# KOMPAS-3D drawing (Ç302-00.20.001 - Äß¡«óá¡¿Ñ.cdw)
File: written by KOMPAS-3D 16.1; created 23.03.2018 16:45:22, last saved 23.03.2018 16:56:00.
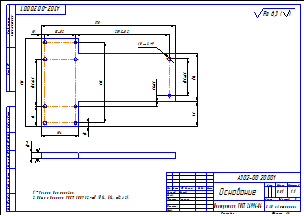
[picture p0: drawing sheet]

Sheet 1: A3, landscape

Title block, sheet 1: name: Основание; designation: А302-00.20.001; material: Полипропилен  ГОСТ 26996-86; mass: 0,81; scale: 1:1; sheets: 1; organisation: ЗАО «Астерион»; sheet format: A3; stored path: \\192.168.87.28\Konstructor_doc\Мембранные насосы\Мембранный электропривод\А302-00.00.000 - ASTRA-302 (МЭ200)\Чертежи\А302-00.20.001 - Основание.cdw; drawn by: Милов; technical control: Лучихин

Views: Вид 1, Спереди, Проекционный вид 2
Referenced files in Z:\Мембранные насосы\Мембранный электропривод\А302-00.00.000 - ASTRA-302 (МЭ200)\3Д\: А302-00.20.001 - Основание.m3d
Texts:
  *Размер для справок.
  Общие допуски ГОСТ 30893.2-mK (H14, h14,  t2/2).
  Ra 6,3
  Ra 6,3 ( )
Dimensions and other numbers on the sheet: 10; 56; 130±0,2; 29±0,2; 102±0,2; 134; 69; 243; 223; 85±0,2; 370; 10 отв.; 9; 259,5±0,2; 104; 15; 1:1; 1; 0,81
